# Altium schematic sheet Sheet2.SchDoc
size A
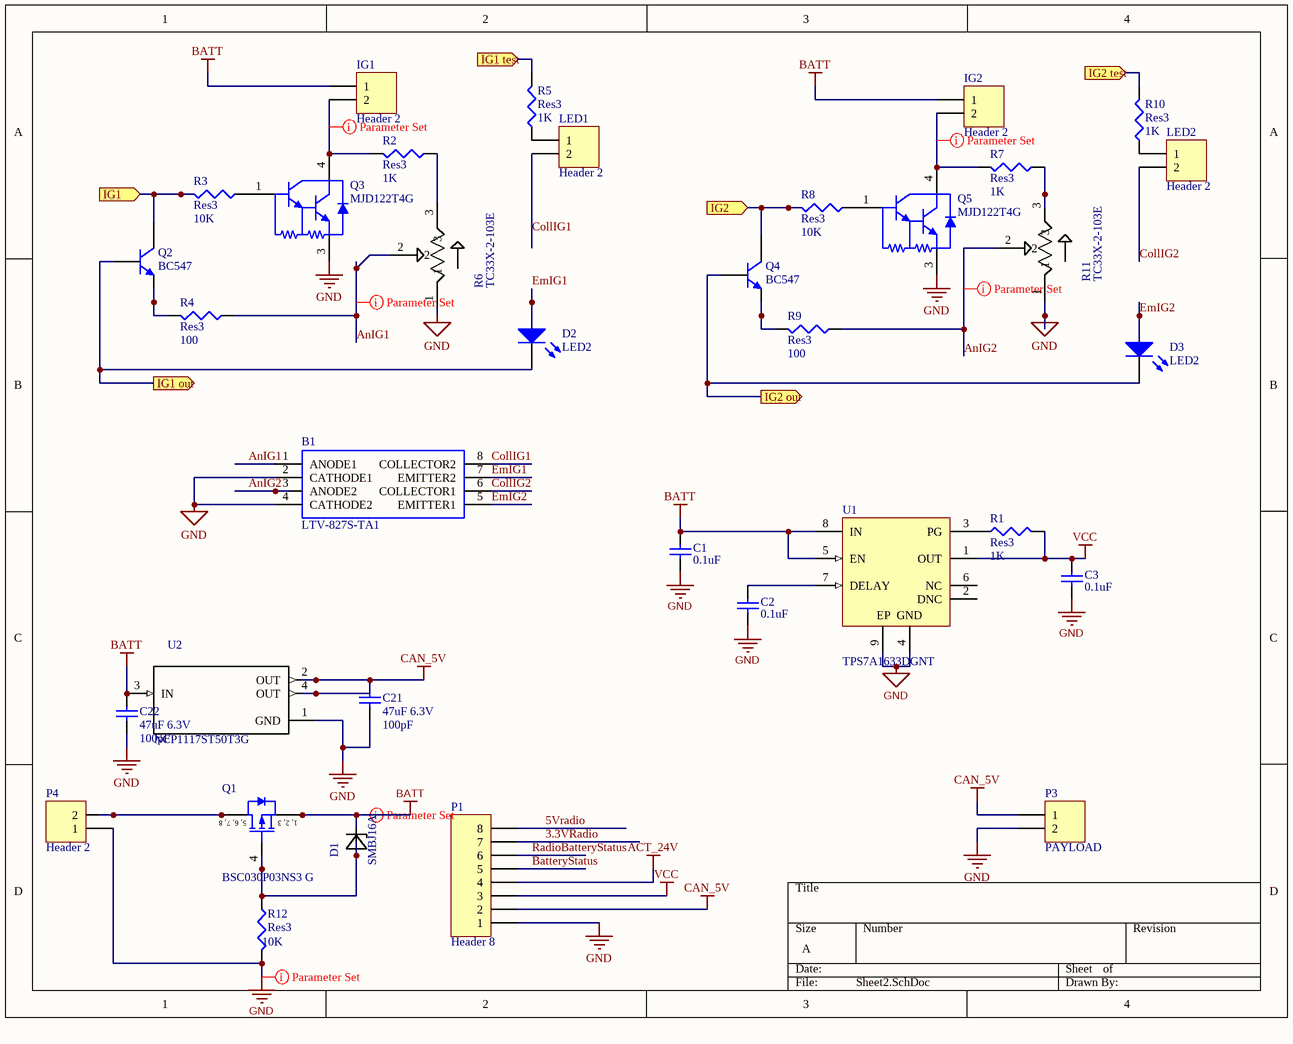
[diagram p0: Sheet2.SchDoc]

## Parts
B1  LTV-827S-TA1  [SOP254P1016X460-8N]
C1  value 0.1uF  [C1206]  (hidden comment: Cap Semi)
C2  value 0.1uF  [C1206]  (hidden comment: Cap Semi)
C3  value 0.1uF  [C1206]  (hidden comment: Cap Semi)
C21  47uF 6.3V  value 100pF  [1206]
C22  47uF 6.3V  value 100pF  [1206]
D1  SMBJ16A  [DO214AA_SMBJ16A(Primary)]
D2  LED2  [3.2X1.6X1.1]
D3  LED2  [3.2X1.6X1.1]
IG1  Header 2  [HDR1X2]
IG2  Header 2  [HDR1X2]
LED1  Header 2  [HDR1X2]
LED2  Header 2  [HDR1X2]
P1  Header 8  [HDR1X8]
P3  PAYLOAD  [HDR1X2]
P4  Header 2  [HDR1X2]
Q1  BSC030P03NS3 G  [INF-PG-TDSON-8-1_V]
Q2  BC547  [TO-92A]
Q3  MJD122T4G  [ONSC-DPAK-3-369C-01_V]
Q4  BC547  [TO-92A]
Q5  MJD122T4G  [ONSC-DPAK-3-369C-01_V]
R1  Res3  value 1K  [J1-0603]
R2  Res3  value 1K  [J1-0603]
R3  Res3  value 10K  [J1-0603]
R4  Res3  value 100  [J1-0603]
R5  Res3  value 1K  [J1-0603]
R6  TC33X-2-103E  [TRIM_TC33X-2-103E]
R7  Res3  value 1K  [J1-0603]
R8  Res3  value 10K  [J1-0603]
R9  Res3  value 100  [J1-0603]
R10  Res3  value 1K  [J1-0603]
R11  TC33X-2-103E  [TRIM_TC33X-2-103E]
R12  Res3  value 10K  [J1-0603]
U1  TPS7A1633DGNT  [TI-DGN8-1790X1470TP_N]
U2  NCP1117ST50T3G  [SOT230P700X180-4N]

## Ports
IG1 (in), IG1 out (out), IG1 test (in), IG2 (in), IG2 out (out), IG2 test (in)

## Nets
ACT_24V: P1.4
BATT: C1.2 C22.1 D1.C IG1.1 IG2.1 Q1.1(SOURCE) Q1.2(SOURCE) Q1.3(SOURCE) U1.5(EN) U1.8(IN) U2.3(IN)
CAN_5V: C21.1 P1.2 P3.1 U2.2(OUT) U2.4(OUT)
GND: B1.2(CATHODE1) B1.4(CATHODE2) C1.1 C2.1 C3.1 C21.2 C22.2 P1.1 P3.2 P4.1 Q3.3(E) Q5.3(E) R6.1 R11.1 R12.2 U1.4(GND) U1.9(EP) U2.1(GND)
VCC: C3.2 P1.3 R1.2 U1.1(OUT)
3.3VRadio: P1.7
5Vradio: P1.8
AnIG1: B1.1(ANODE1) R4.1 R6.2
AnIG2: B1.3(ANODE2) R9.1 R11.2
BatteryStatus: P1.5
CollIG1: B1.8(COLLECTOR2) LED1.2
CollIG2: B1.6(COLLECTOR1) LED2.2
EmIG1: B1.7(EMITTER2) D2.1(A)
EmIG2: B1.5(EMITTER1) D3.1(A)
IG1: Q2.3(C) R3.2 ; port IG1
IG1 out: D2.2(K) Q2.2(B) ; port IG1 out
IG1 test: R5.2 ; port IG1 test
IG2: Q4.3(C) R8.2 ; port IG2
IG2 out: D3.2(K) Q4.2(B) ; port IG2 out
IG2 test: R10.2 ; port IG2 test
RadioBatteryStatus: P1.6
NetC2_2: C2.2 U1.7(DELAY)
NetD1_A: D1.A Q1.4(GATE) R12.1
NetIG1_2: IG1.2 Q3.4(C) R2.2
NetIG2_2: IG2.2 Q5.4(C) R7.2
NetLED1_1: LED1.1 R5.1
NetLED2_1: LED2.1 R10.1
NetP4_2: P4.2 Q1.5(DRAIN) Q1.6(DRAIN) Q1.7(DRAIN) Q1.8(DRAIN)
NetQ2_1: Q2.1(E) R4.2
NetQ3_1: Q3.1(B) R3.1
NetQ4_1: Q4.1(E) R9.2
NetQ5_1: Q5.1(B) R8.1
NetR1_1: R1.1 U1.3(PG)
NetR2_1: R2.1 R6.3
NetR7_1: R7.1 R11.3

Not connected (* = marked no-connect by the designer): U1 2(DNC) 6(NC)

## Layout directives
rule Width Constraint [Pref Width = 0.4mm    Min Width = 0.4mm    Max Width = 0.4mm]: AnIG1, AnIG2, BATT, GND, NetIG1_2, NetIG2_2

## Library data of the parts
B1 = LTV-827S-TA1: Lite-On LTV-827S-TA1 DC Input Transistor Output Dual Optocoupler, Surface Mount, 8-Pin PDIP; Geometry.Height: 4.6mm
C1-C3 = Cap Semi: Capacitor (Semiconductor SIM Model)
C21 C22 = C1206: Ceramic Chip Capacitor - Standard
D1 = SMBJ16A: Diode TVS Single Uni-Dir 16V 600W 2-Pin DO-214AA T/R; MF: ON Semiconductor
D2 D3 = LED2: Typical RED, GREEN, YELLOW, AMBER GaAs LED
IG1 IG2 LED1 LED2 P3 P4 = Header 2: Header, 2-Pin
P1 = Header 8: Header, 8-Pin
Q1 = BSC030P03NS3 G: P-Channel OptiMOS P3 Power-Transistor, -30 V VDS, -100 A ID, -55 to 150 degC, PG-TDSON-8-1, Reel, Green; Manufacturer: Infineon; Green: TRUE; ID (max): -100 A; IDpuls (max): -200 A; Pto t (max): 125 W; QG: 137 nC; RDS (on) (max): 3 mOhm; Rth: 1 K/W; VDS (max): -30 V; VGS(th) (max): -1.9 V; VGS(th) (min): -3.1 V
Q2 Q4 = 2N3904: NPN General Purpose Amplifier
Q3 Q5 = MJD122T4G: Complementary Darlington Power Transistor, 3-Pin DPAK, Pb-Free, Tape and Reel; Manufacturer: On Semiconductor; hFE Max (k): 12; IC Continuous (A): 8; Polarity: NPN
R1-R5 R7-R10 R12 = Res3: Resistor
R6 R11 = TC33X-2-103E: Res Trimmer 10K Ohm 25% 0.1W_1/10W_ 1_Elec_/1_Mech_Turn _3 X 3.8mm_ Foot Print SMD Embossed T/R; MF: Bourns
U1 = TPS7A1633DGNT: Single Output LDO, 100 mA, Fixed 3.3 V Output, 3 to 60 V Input, with Enable and Power Good, 8-pin MSOP (DGN), -40 to 125 degC, Green (RoHS & no Sb/Br); Manufacturer: Texas Instruments; Accuracy(%): 2; Fixed Output Options(V): 3.3; Iout(Max)(A): 0.1; Iq(Typ)(mA): 0.004; Power Good: TRUE; Rating: Catalog; SubFamily: Single Channel LDO; Vdo(Typ)(mV): 60; Vin(Min)(V): 3
U2 = NCP1117ST50T3G: MF: ON Semiconductor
